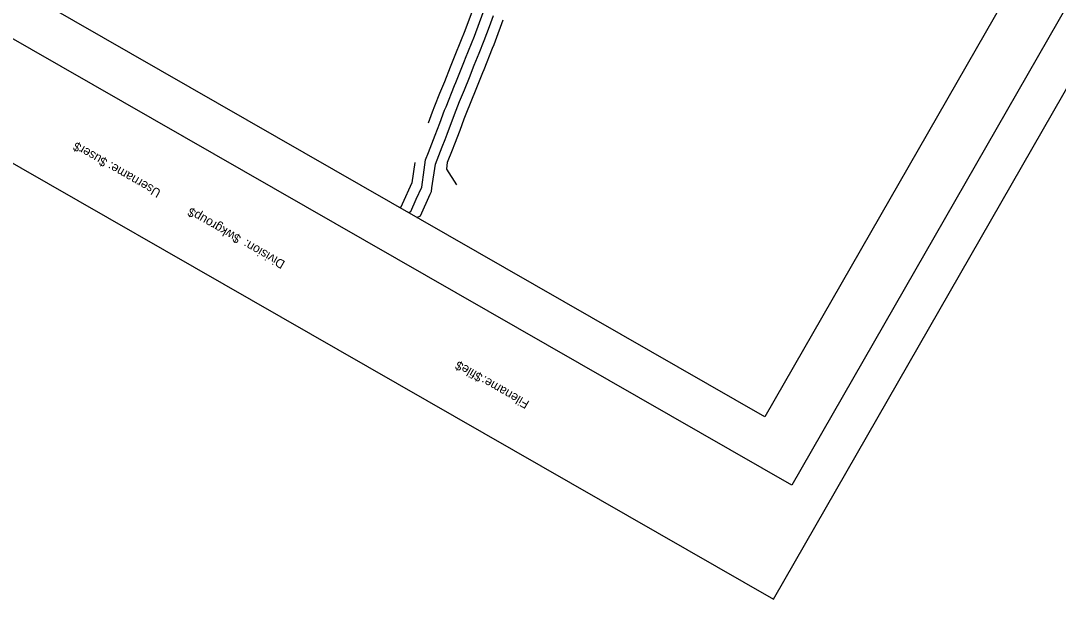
# Model space of a CAD drawing. Extents: x 1160447 to 1162032, y 616022 to 618272.
# Drawn here: x 1160642.1 to 1161030.2, y 616022.2 to 616238.7 of the extents above; entities that cross this region are included whole.
import ezdxf

# ---------------------------------------------------------------- set-up
doc = ezdxf.new("R2010")
doc.units = 0
for name, color, linetype in [('BORDER', 7, 'Continuous'), ('D_Contours_Minor', 7, 'Continuous'), ('PLOT BOUNDARY', 7, 'Continuous'), ('Plot Boundary_1', 7, 'Continuous')]:
    doc.layers.add(name, color=color, linetype=linetype)

msp = doc.modelspace()

# ---------------------------------------------------------------- linework, layer by layer
at = {"layer": 'BORDER'}
msp.add_lwpolyline([(1160475.14, 616326.08), (1160873.19, 617020.03), (1161328.59, 616758.81), (1160930.55, 616064.86)], close=True, dxfattribs=at)
at = {"layer": 'D_Contours_Minor'}
for points in [[(1160794.65, 616200.52), (1160796.18, 616204.63), (1160797, 616206.83), (1160798.93, 616211.58), (1160800.73, 616216.03), (1160802.92, 616221.52), (1160804.41, 616225.26), (1160806.99, 616231.65), (1160808.12, 616234.48), (1160810.96, 616242.11), (1160811.59, 616243.79), (1160814.96, 616253.08), (1160814.98, 616253.13), (1160815.11, 616253.48)], [(1160787.11, 616166.92), (1160787.99, 616167.36), (1160790.06, 616171.94), (1160792.09, 616176.42), (1160793.02, 616182.94), (1160793.56, 616186.64), (1160794.63, 616189.36), (1160797.19, 616195.91), (1160798.89, 616200.44), (1160800.67, 616205.23), (1160801.21, 616206.55), (1160804.41, 616214.45), (1160804.88, 616215.64), (1160808.09, 616223.69), (1160808.49, 616224.67), (1160811.8, 616232.91), (1160815.14, 616241.88)], [(1160790.33, 616165.07), (1160791.64, 616165.73), (1160795.3, 616173.82), (1160795.74, 616174.81), (1160795.95, 616176.24), (1160797.22, 616185.03), (1160799.76, 616191.5), (1160800.86, 616194.31), (1160801.59, 616196.26), (1160804.34, 616203.64), (1160806.29, 616208.46), (1160808.08, 616212.87), (1160809.94, 616217.52), (1160811.77, 616222.11), (1160813.56, 616226.56), (1160815.48, 616231.34), (1160817.42, 616236.54), (1160818.96, 616240.67)], [(1160805.29, 616177.3), (1160801.48, 616183.13), (1160801.47, 616183.15), (1160801.45, 616183.18), (1160801.8, 616185.75), (1160803.62, 616190.39), (1160804.52, 616192.71), (1160806.43, 616197.8), (1160808.01, 616202.05), (1160811.38, 616210.36), (1160811.75, 616211.28), (1160814.99, 616219.4), (1160815.44, 616220.54), (1160818.63, 616228.46), (1160819.16, 616229.78), (1160819.7, 616231.21), (1160822.64, 616239.12)], [(1160789.52, 616185.65), (1160788.43, 616178.04), (1160784.82, 616170.05), (1160784.33, 616168.98), (1160783.89, 616168.76)]]:
    msp.add_lwpolyline(points, dxfattribs=at)
at = {"layer": 'PLOT BOUNDARY'}
msp.add_lwpolyline([(1160923.68, 616022.15), (1161346.6, 616759.47), (1160869.52, 617033.12), (1160446.59, 616295.81)], close=True, dxfattribs=at)
at = {"layer": 'Plot Boundary_1'}
msp.add_lwpolyline([(1160500.57, 616331.28), (1160855.78, 616950.54), (1161275.71, 616709.67), (1160920.5, 616090.41)], close=True, dxfattribs=at)

# ---------------------------------------------------------------- texts
at = {"layer": 'BORDER'}
for s, p in [('$user$', (1160674.8, 616186.69)), ('Username:', (1160694.85, 616175.19)), ('$wkgroup$', (1160724.77, 616158.02)), ('Division:', (1160741.27, 616148.56)), ('$file$', (1160815.17, 616106.17)), ('Filename:', (1160832.64, 616096.15))]:
    msp.add_text(s, height=3.348, rotation=150.1613, dxfattribs=at).set_placement(p)

doc.saveas('drawing.dxf')
